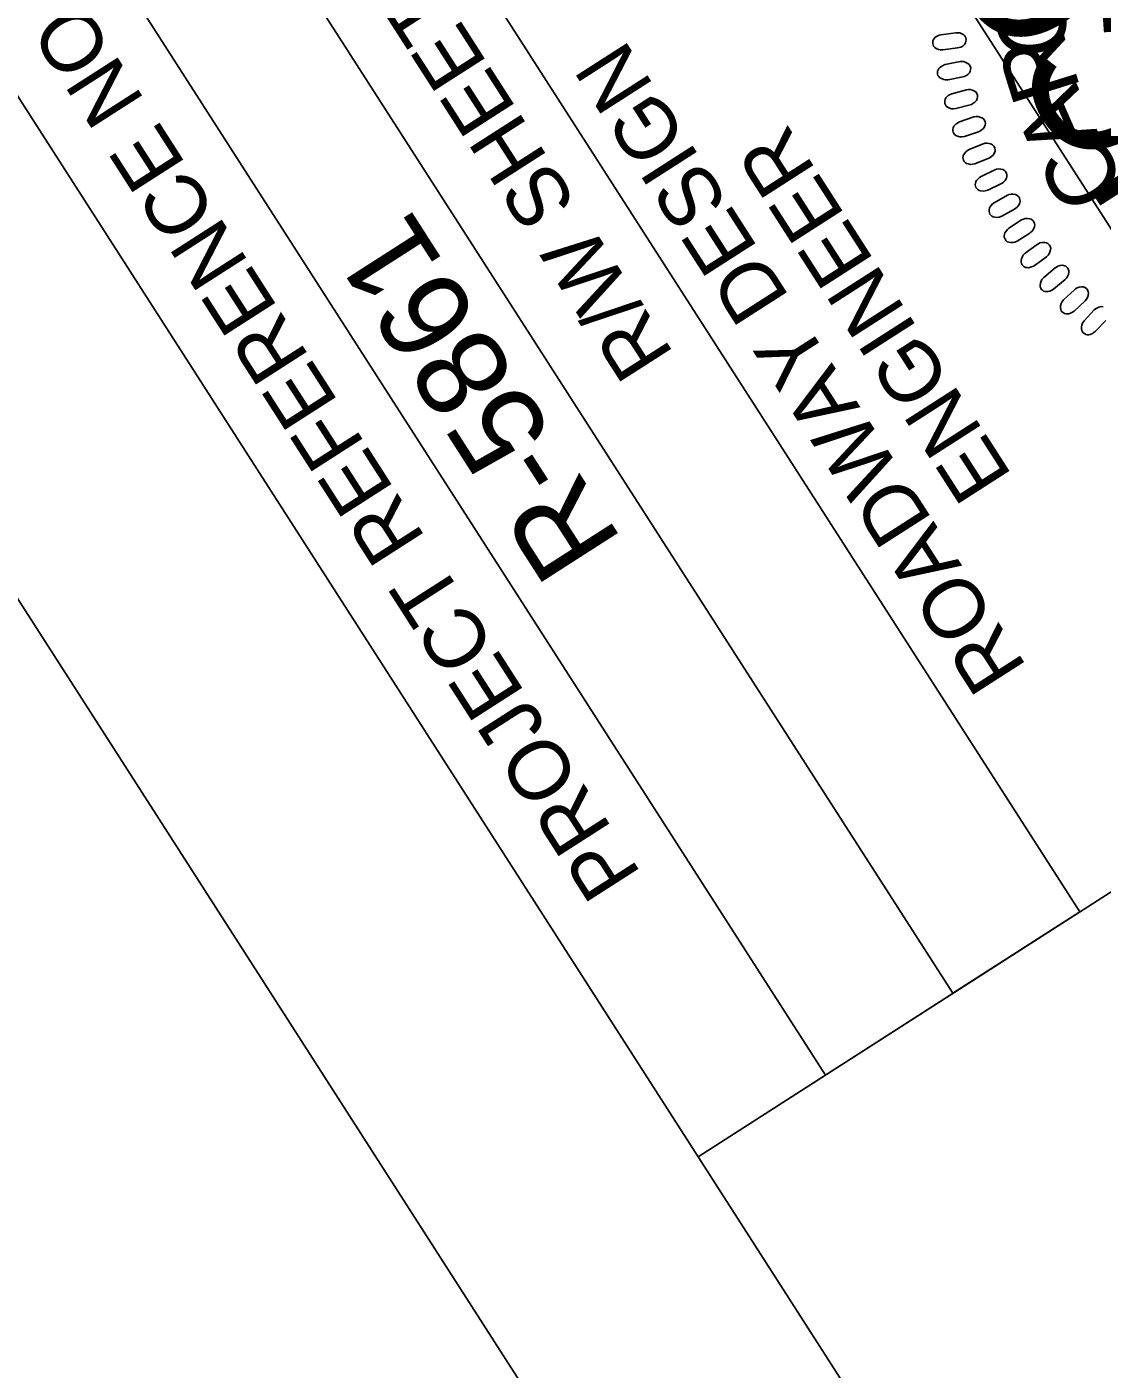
# Model space of a CAD drawing. Extents: x 476646 to 478477, y 498681 to 500689.
# Drawn here: x 476726.9 to 476816, y 499910 to 500021.3 of the extents above; entities that cross this region are included whole.
import ezdxf

# ---------------------------------------------------------------- set-up
doc = ezdxf.new("R2010")
doc.units = 0
for name, color, linetype in [('Sheet Data Field CELL', 7, 'Continuous'), ('Sheet PE Seal Cell', 7, 'Continuous'), ('Sheet Plan CELL', 7, 'Continuous'), ('Sheet Plot Border Outside CELL', 7, 'Continuous'), ('Sheet Sticker Incomplete CELL', 7, 'Continuous')]:
    doc.layers.add(name, color=color, linetype=linetype)

msp = doc.modelspace()

# ---------------------------------------------------------------- linework, layer by layer
at = {"layer": 'Sheet PE Seal Cell'}
for points in [[(476804.06, 500019.52), (476802.84, 500019.36), (476802.62, 500019.36), (476802.47, 500019.4), (476802.29, 500019.49), (476802.17, 500019.57), (476802.07, 500019.67), (476802.02, 500019.77), (476801.99, 500019.88), (476801.99, 500019.99), (476802.01, 500020.11), (476802.05, 500020.23), (476802.14, 500020.34), (476802.21, 500020.41), (476802.35, 500020.5), (476802.52, 500020.58), (476802.67, 500020.62), (476803.92, 500020.79), (476804.09, 500020.79), (476804.23, 500020.77), (476804.4, 500020.7), (476804.56, 500020.61), (476804.65, 500020.52), (476804.73, 500020.37), (476804.77, 500020.23), (476804.75, 500020.07), (476804.71, 500019.96), (476804.63, 500019.82), (476804.48, 500019.68), (476804.31, 500019.59), (476804.18, 500019.55)], [(476804.48, 500017.12), (476803.28, 500016.89), (476803.05, 500016.88), (476802.91, 500016.91), (476802.72, 500016.99), (476802.59, 500017.06), (476802.49, 500017.15), (476802.43, 500017.25), (476802.39, 500017.36), (476802.39, 500017.47), (476802.4, 500017.59), (476802.44, 500017.71), (476802.51, 500017.83), (476802.58, 500017.9), (476802.71, 500018), (476802.88, 500018.09), (476803.03, 500018.14), (476804.26, 500018.39), (476804.43, 500018.4), (476804.58, 500018.39), (476804.75, 500018.33), (476804.91, 500018.24), (476805.01, 500018.16), (476805.1, 500018.02), (476805.15, 500017.88), (476805.13, 500017.72), (476805.11, 500017.61), (476805.03, 500017.47), (476804.89, 500017.32), (476804.73, 500017.22), (476804.6, 500017.16)], [(476805.09, 500014.81), (476803.91, 500014.5), (476803.69, 500014.48), (476803.54, 500014.49), (476803.34, 500014.56), (476803.21, 500014.62), (476803.11, 500014.71), (476803.04, 500014.8), (476803, 500014.91), (476802.99, 500015.02), (476802.99, 500015.14), (476803.02, 500015.26), (476803.09, 500015.39), (476803.15, 500015.46), (476803.28, 500015.57), (476803.44, 500015.67), (476803.58, 500015.73), (476804.8, 500016.06), (476804.97, 500016.08), (476805.11, 500016.07), (476805.29, 500016.02), (476805.45, 500015.95), (476805.56, 500015.88), (476805.65, 500015.74), (476805.71, 500015.6), (476805.71, 500015.45), (476805.69, 500015.33), (476805.62, 500015.18), (476805.49, 500015.03), (476805.33, 500014.91), (476805.22, 500014.85)], [(476805.79, 500012.58), (476804.62, 500012.19), (476804.4, 500012.16), (476804.25, 500012.16), (476804.06, 500012.22), (476803.92, 500012.28), (476803.81, 500012.36), (476803.74, 500012.44), (476803.68, 500012.54), (476803.67, 500012.66), (476803.66, 500012.78), (476803.68, 500012.9), (476803.75, 500013.03), (476803.8, 500013.11), (476803.92, 500013.22), (476804.08, 500013.33), (476804.22, 500013.41), (476805.41, 500013.81), (476805.58, 500013.84), (476805.73, 500013.84), (476805.91, 500013.8), (476806.07, 500013.74), (476806.18, 500013.67), (476806.29, 500013.54), (476806.35, 500013.41), (476806.36, 500013.25), (476806.35, 500013.14), (476806.29, 500012.99), (476806.17, 500012.82), (476806.02, 500012.7), (476805.9, 500012.63)], [(476806.63, 500010.38), (476805.49, 500009.92), (476805.28, 500009.88), (476805.13, 500009.87), (476804.93, 500009.91), (476804.79, 500009.96), (476804.67, 500010.04), (476804.6, 500010.12), (476804.54, 500010.22), (476804.51, 500010.33), (476804.5, 500010.45), (476804.51, 500010.57), (476804.57, 500010.7), (476804.62, 500010.79), (476804.73, 500010.91), (476804.88, 500011.03), (476805.02, 500011.11), (476806.18, 500011.58), (476806.35, 500011.63), (476806.49, 500011.64), (476806.67, 500011.61), (476806.85, 500011.56), (476806.96, 500011.5), (476807.07, 500011.38), (476807.14, 500011.25), (476807.16, 500011.09), (476807.16, 500010.98), (476807.11, 500010.82), (476807, 500010.65), (476806.86, 500010.52), (476806.75, 500010.44)], [(476807.65, 500008.26), (476806.55, 500007.73), (476806.33, 500007.67), (476806.18, 500007.66), (476805.98, 500007.68), (476805.84, 500007.72), (476805.72, 500007.79), (476805.64, 500007.87), (476805.57, 500007.96), (476805.54, 500008.07), (476805.52, 500008.19), (476805.53, 500008.31), (476805.57, 500008.45), (476805.62, 500008.54), (476805.73, 500008.66), (476805.86, 500008.79), (476806, 500008.88), (476807.13, 500009.43), (476807.29, 500009.48), (476807.44, 500009.5), (476807.62, 500009.49), (476807.79, 500009.45), (476807.91, 500009.4), (476808.03, 500009.28), (476808.11, 500009.15), (476808.14, 500009), (476808.14, 500008.88), (476808.1, 500008.73), (476808, 500008.55), (476807.87, 500008.41), (476807.76, 500008.33)], [(476808.78, 500006.17), (476807.71, 500005.58), (476807.5, 500005.5), (476807.35, 500005.48), (476807.15, 500005.5), (476807.01, 500005.53), (476806.88, 500005.59), (476806.8, 500005.66), (476806.72, 500005.75), (476806.69, 500005.86), (476806.66, 500005.98), (476806.66, 500006.1), (476806.69, 500006.24), (476806.73, 500006.33), (476806.83, 500006.46), (476806.96, 500006.6), (476807.09, 500006.69), (476808.18, 500007.31), (476808.34, 500007.37), (476808.49, 500007.4), (476808.67, 500007.4), (476808.85, 500007.37), (476808.96, 500007.33), (476809.09, 500007.22), (476809.18, 500007.1), (476809.22, 500006.95), (476809.23, 500006.83), (476809.2, 500006.67), (476809.11, 500006.48), (476808.99, 500006.34), (476808.89, 500006.25)], [(476810.03, 500004.17), (476809, 500003.51), (476808.8, 500003.42), (476808.65, 500003.39), (476808.45, 500003.4), (476808.3, 500003.42), (476808.17, 500003.47), (476808.08, 500003.54), (476808.01, 500003.62), (476807.96, 500003.73), (476807.92, 500003.84), (476807.92, 500003.96), (476807.95, 500004.1), (476807.98, 500004.2), (476808.07, 500004.34), (476808.19, 500004.48), (476808.31, 500004.59), (476809.36, 500005.27), (476809.52, 500005.34), (476809.66, 500005.38), (476809.84, 500005.39), (476810.02, 500005.37), (476810.14, 500005.33), (476810.28, 500005.23), (476810.37, 500005.12), (476810.42, 500004.97), (476810.44, 500004.86), (476810.42, 500004.7), (476810.34, 500004.5), (476810.23, 500004.35), (476810.13, 500004.26)], [(476810.64, 500003.24), (476809.65, 500002.51), (476809.5, 500002.35), (476809.42, 500002.23), (476809.35, 500002.04), (476809.32, 500001.9), (476809.32, 500001.76), (476809.35, 500001.65), (476809.4, 500001.55), (476809.48, 500001.47), (476809.58, 500001.39), (476809.69, 500001.34), (476809.83, 500001.32), (476809.93, 500001.31), (476810.09, 500001.35), (476810.27, 500001.41), (476810.41, 500001.48), (476811.43, 500002.22), (476811.55, 500002.34), (476811.64, 500002.46), (476811.71, 500002.62), (476811.76, 500002.8), (476811.77, 500002.92), (476811.72, 500003.09), (476811.65, 500003.22), (476811.53, 500003.31), (476811.43, 500003.37), (476811.27, 500003.41), (476811.06, 500003.41), (476810.88, 500003.36), (476810.76, 500003.3)], [(476812.13, 500001.3), (476811.19, 500000.51), (476811.04, 500000.34), (476810.97, 500000.21), (476810.91, 500000.02), (476810.89, 499999.87), (476810.9, 499999.73), (476810.94, 499999.63), (476810.99, 499999.53), (476811.08, 499999.46), (476811.18, 499999.38), (476811.29, 499999.34), (476811.44, 499999.33), (476811.54, 499999.33), (476811.7, 499999.37), (476811.87, 499999.44), (476812.01, 499999.53), (476812.98, 500000.33), (476813.09, 500000.45), (476813.17, 500000.58), (476813.24, 500000.75), (476813.27, 500000.93), (476813.27, 500001.05), (476813.22, 500001.21), (476813.14, 500001.34), (476813.01, 500001.43), (476812.9, 500001.47), (476812.75, 500001.51), (476812.54, 500001.49), (476812.36, 500001.43), (476812.24, 500001.37)], [(476813.73, 499999.49), (476812.84, 499998.65), (476812.7, 499998.47), (476812.64, 499998.34), (476812.59, 499998.14), (476812.58, 499997.99), (476812.6, 499997.86), (476812.64, 499997.75), (476812.7, 499997.66), (476812.79, 499997.59), (476812.9, 499997.52), (476813.01, 499997.49), (476813.16, 499997.48), (476813.26, 499997.49), (476813.41, 499997.55), (476813.58, 499997.63), (476813.72, 499997.72), (476814.63, 499998.58), (476814.74, 499998.71), (476814.81, 499998.84), (476814.86, 499999.01), (476814.89, 499999.19), (476814.88, 499999.32), (476814.82, 499999.47), (476814.73, 499999.59), (476814.59, 499999.68), (476814.49, 499999.72), (476814.33, 499999.74), (476814.12, 499999.71), (476813.95, 499999.64), (476813.83, 499999.57)]]:
    msp.add_lwpolyline(points, close=True, dxfattribs=at)
msp.add_lwpolyline([(476816.11, 499998.08), (476815.95, 499998.09), (476815.75, 499998.05), (476815.58, 499997.96), (476815.47, 499997.89), (476815.37, 499997.81), (476814.53, 499996.91), (476814.41, 499996.72), (476814.35, 499996.58), (476814.32, 499996.38), (476814.32, 499996.24), (476814.34, 499996.1), (476814.39, 499996), (476814.46, 499995.91), (476814.56, 499995.85), (476814.67, 499995.79), (476814.78, 499995.76), (476814.93, 499995.76), (476815.03, 499995.78), (476815.18, 499995.84), (476815.34, 499995.94), (476815.47, 499996.04), (476816.33, 499996.95)], dxfattribs=at)
at = {"layer": 'Sheet Plan CELL'}
for p, q in [((476803.67, 499941.18), (476695.63, 500109.53)), ((476803.67, 499941.18), (476695.63, 500109.53)), ((476793.12, 499934.4), (476685.11, 500102.78)), ((476803.67, 499941.18), (476814.18, 499947.92))]:
    msp.add_line(p, q, dxfattribs=at)
for points in [[(476674.53, 500096.04), (477484.51, 498833.48), (478368.28, 499400.46), (477558.31, 500662.99)], [(476782.55, 499927.63), (476814.18, 499947.92), (476760.16, 500032.13), (476854.86, 500092.89), (476908.85, 500008.67)]]:
    msp.add_lwpolyline(points, close=True, dxfattribs=at)
at = {"layer": 'Sheet Plot Border Outside CELL'}
msp.add_lwpolyline([(478477.12, 499272.48), (477568.08, 500689.45), (476646.44, 500098.18), (477555.48, 498681.21)], close=True, dxfattribs=at)
at = {"layer": 'Sheet Sticker Incomplete CELL'}
msp.add_lwpolyline([(476847.19, 500000.64), (476827.41, 499987.95), (476748.03, 500111.68), (476767.81, 500124.37)], close=True, dxfattribs=at)

# ---------------------------------------------------------------- texts
at = {"layer": 'Sheet Data Field CELL'}
msp.add_text('R-5861', height=7.5, rotation=122.6818, dxfattribs=at).set_placement((476776.36, 499978.63))
at = {"layer": 'Sheet PE Seal Cell'}
for s, rotation, p in [('O', 94.3121, (476813.22, 500018.95)), ('R', 107.2908, (476814.27, 500016.11)), ('A', 113.7801, (476815.87, 500012.14)), ('C', 120.2695, (476818.17, 500008.17))]:
    msp.add_text(s, height=5.67, rotation=rotation, dxfattribs=at).set_placement(p)
at = {"layer": 'Sheet Plan CELL'}
for s, height, p in [('R/W SHEET NO.', 5.0001, (476780.62, 499994.12)), ('PROJECT REFERENCE NO.', 5.0001, (476777.91, 499951.03)), ('ROADWAY DESIGN', 5.0001, (476809.86, 499968.17)), ('ENGINEER', 5, (476808.65, 499984.01))]:
    msp.add_text(s, height=height, rotation=122.6818, dxfattribs=at).set_placement(p)
at = {"layer": 'Sheet Sticker Incomplete CELL'}
for s, height, p in [('INCOMPLETE PLANS', 11.52, (476832.51, 500001.86)), ('DO NOT USE FOR R/W ACQUISITION', 5.76, (476836.6, 500008.35))]:
    msp.add_text(s, height=height, rotation=122.6818, dxfattribs=at).set_placement(p)

doc.saveas('drawing.dxf')
